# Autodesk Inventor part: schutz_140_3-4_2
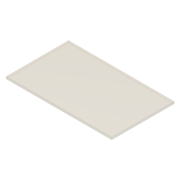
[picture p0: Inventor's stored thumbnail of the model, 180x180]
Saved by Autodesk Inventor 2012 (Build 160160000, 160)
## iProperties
Company: CAD-Verlag
Part Number: schutz_140_3-4_2
Document SubType Name: Sheet Metal
Created: 2004-09
Material: Standard
Designer: Greiling
Manufacturer: Standard
Standards Organization: Custom
Density: 1 g/cm^3
Sheet Metal Rule: Standard
Control State: 0
Master: False
Checked Out: False
Shininess: 64.0
Length Units: 11269
Angle Units: 11279
Time Units: 11290
Mass Units: 11283
Length Display Precision: 3
Angle Display Precision: 2
Compacted: True
Density: 0.0
Volumn: 0.0
Area: 0.0
PropertySet Name: Model Information
Author: Jürgen Kronas
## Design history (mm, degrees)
node "Fläche1"
  sketch "Skizze1"
    geometry: L1 (0, 105.6)-(0, -17.6) reference; L2 (-29.8, 0)-(178.8, 0) reference; L3 (-29.8, 0)-(178.8, 0) reference; L4 (0, -17.6)-(0, 105.6) reference; L5 (0, 0)-(149, 0); L6 (149, 0)-(149, 88); L7 (149, 88)-(0, 88); L8 (0, 88)-(0, 0)
    constraints: 8 end point, 2 parallel, 1 horizontal, 1 perpendicular
    dimensions: "d0" = 149 distance of L6.end L7.end; "d1" = 88 distance between parallel lines of L2 L7
node "Volumenkörper1"
node "Volumenkörpern"
node "Oberflächenkörpern"
feature "Platte1" dims "Objekthöhe" = 3
other parameters: "Biegeradius" = 3 (= Objekthöhe), "BreiteBiegungsfreistellung" = 3 (= Objekthöhe), "TiefeBiegungsfreistellung" = 1.5 (= 0.5 x Objekthöhe), "GrößeEckenfreistellung" = 12 (= 4 x Objekthöhe), "SeamGap" = 0.01, "MinimalRest" = 6 (= 2 x Objekthöhe), "Übergangsradius" = 3 (= Biegeradius), "d2" = 3 (= Biegeradius), "JacobiRadiusGröße" = 3 (= Objekthöhe), "Abstandsgröße" = 3 (= Objekthöhe)
